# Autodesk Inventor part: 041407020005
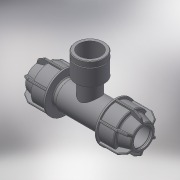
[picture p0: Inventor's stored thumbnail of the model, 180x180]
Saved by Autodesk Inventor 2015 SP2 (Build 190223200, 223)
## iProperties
Created: 2017-08
Part Number: 041407020005
Material: Generic
Description: PLASSON IRRIFIT TEE FEMALE ADAPTOR 20-1/2"-20
Document SubType Name: Modeling
Designer: KIM
Density: 1 g/cm^3
Appearance: Default
Author: KIM
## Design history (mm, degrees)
derived "041407.ipt"
feature "Solid1::041407.ipt"
feature "Solid2::041407.ipt"
tag "TaggingFeature1"
body "Solid1"
other parameters: "d2" = 25, "d4" = 15 deg, "d5" = 23.75, "d6" = 9.5, "d10" = 39, "d16" = 20.4, "d17" = 1.25, "d22" = 26, "d24" = 1.25, "d25" = 35.1, "d26" = 29.25, "d27" = 1.25, "d28" = 135 deg, "d29" = 0.75, "d31" = 1, "d46" = 150 deg, "d49" = 1.95, "d50" = 0, "d58" = 0.6, "d61" = 360 deg, "d63" = 18, "d64" = 45, "d80" = 28.6, "d81" = 0.2, "d94" = 45, "d96" = 24.2203, "d108" = 0.6, "d113" = 13.0417, "d115" = 19.2, "d117" = 16.7679, "d118" = 2.5, "d119" = 16, "d120" = 18.631, "d121" = 0.37262, "d122" = 4.8, "d123" = 2.5, "d128" = 24.2203, "d130" = 0, "d132" = 0, "G_" = 18.631, "E_" = 39, "l_" = 25, "l_1" = 16, "A_" = 45
